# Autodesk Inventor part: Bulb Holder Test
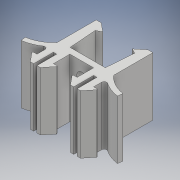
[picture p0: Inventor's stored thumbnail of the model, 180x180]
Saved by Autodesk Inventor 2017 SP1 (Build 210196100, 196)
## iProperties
Created: 2016-12
Part Number: Bulb Holder Test
Material: Generic
Document SubType Name: Modeling
Designer: HP_ELITE
Density: 1 g/cm^3
Appearance: Default
Author: HP_ELITE
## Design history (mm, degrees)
sketch "Sketch1"
  geometry: L1 (0, -12.369)-(-5.345, -12.369); L2 (-5.995, -4.119)-(-4.495, -3.319); L3 (-7.095, -1.169)-(-8.595, -1.169); L4 (-8.595, -1.169)-(-8.595, -14.169); L5 (-8.595, -14.169)-(0, -14.169) reference; L6 (0, -14.169)-(0, -12.369); L7 (-4.495, -3.319)-(-7.095, -1.169); L8 (-5.345, -12.369)-(-5.995, -4.119); 1 further point
  constraints: 16 end point, 3 perpendicular, 2 horizontal, 1 parallel, 1 vertical alignment, 1 other
  dimensions: "d1" = 1.8 distance of L5.end L1.start; "d4" = 1.5 horizontal distance of L2.start L2.end; "d6" = 13 distance of L3.end L4.end; "d7" = 9.05 distance from line of L2.end L1; "d8" = 8.25 vertical distance of L1.end L2.start; "d9" = 0.65 horizontal distance of L1.end L2.start; "d10" = 1.5 distance of L3.start L3.end; "d11" = 3.25 distance from line of L4 L1.end
extrude "Extrusion1" new body sketch "Sketch1" stored distance "d12" = 17.75; taper "d13" = 0 deg
sketch "Sketch3"
  geometry: L1 (-8.595, -14.169)-(-8.595, -19.169); L2 (-8.595, -19.169)-(-10.095, -19.169); L3 (-10.095, -19.169)-(-7.595, -22.169); L4 (-7.595, -22.169)-(-6.595, -22.169); L5 (-6.595, -22.169)-(-6.595, -16.169); L6 (-6.595, -16.169)-(-6.095, -16.169); L7 (-8.595, -14.169)-(0, -14.169) reference; L8 (-6.095, -16.169)-(-6.095, -15.003); L9 (-3.595, -14.169)-(-3.595, -19.169); L10 (-3.595, -19.169)-(-2.095, -19.169); L11 (-2.095, -19.169)-(-4.595, -22.169); L12 (-4.595, -22.169)-(-5.595, -22.169); L13 (-5.595, -22.169)-(-5.595, -16.169); L14 (-5.595, -16.169)-(-6.095, -16.169); L15 (-8.595, -14.169)-(-3.595, -14.169); L16 (0, -14.169)-(-8.595, -14.169) reference; 1 further point
  constraints: 28 end point, 6 symmetric about line, 3 vertical, 2 perpendicular, 1 collinear, 1 parallel
  dimensions: "d19" = 8 distance between parallel lines of L7 L4; "d21" = 2 distance between parallel lines of L5 L1; "d22" = 1.5 distance of L1.end L2.end; "d23" = 5 distance of L1.start L1.end; "d24" = 2.5 horizontal distance of L2.end L3.end; "d25" = 0.5 distance of L5.end L6.end; "d26" = 6 distance of L4.end L5.end
extrude "Extrusion3" join sketch "Sketch3" stored distance "d27" = 21.25; taper "d28" = 0 deg
sketch "Sketch4"
  geometry: L1 (-7.938, -12.323)-(-6.134, -12.323); L2 (-14.799, -16.476)-(-14.622, -17.967); A1 r 12 centre (-16.393, -6.098) between (-14.622, -17.967) and (-6.134, -12.323); A2 r 10.5 centre (-16.393, -6.098) between (-14.799, -16.476) and (-7.938, -12.323); 1 further point
  constraints: 4 end point, 4 point on circle, 2 centre point, 1 horizontal
  dimensions: "d29" = 1.5 radial gap between concentric circles of A1 A2; "d30" = 12 radius of A1
extrude "Extrusion4" join sketch "Sketch4" stored distance "d31" = 10; taper "d32" = 0 deg
mirror "Mirror1"
sketch "Sketch2"
  geometry: L1 (8.595, 11.375)-(8.595, 6.375); L2 (8.595, 13.375)-(8.595, 4.375); C1 r 1.075 at (8.595, 11.375); C2 r 1.075 at (8.595, 6.375); C3 r 1.5 at (8.595, 13.375); C4 r 1.5 at (8.595, 4.375); 2 further points
  constraints: 4 centre point, 4 end point, 3 coincident, 2 equal radius, 2 midpoint, 2 vertical
  dimensions: "d14" = 2.15 diameter of C1; "d15" = 5 distance of L1.start L1.end; "d33" = 3 diameter of C3; "d34" = 9 distance of L2.start L2.end
extrude "Extrusion2" cut sketch "Sketch2" distance "d16" = 21.25; taper "d17" = 0 deg
fillet "Fillet1" dims "d35" = 2
fillet "Fillet2" dims "d36" = 0.75
chamfer "Chamfer1" distance "d37" = 0.4; stored, may be unused: second distance "d38" = 2, angle "d39" = 45 deg
body "Solid1"
